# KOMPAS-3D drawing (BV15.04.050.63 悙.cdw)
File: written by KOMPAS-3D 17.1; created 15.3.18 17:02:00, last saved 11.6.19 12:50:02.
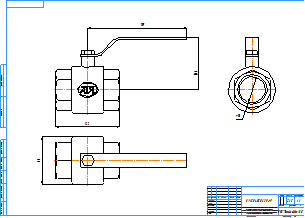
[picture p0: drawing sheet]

Sheet 1: A2, landscape

Title block, sheet 1: name: BV15.04.050.63 Р/Р; material: Внимание! Данный продукт является объектом авторского права ООО «Торговый Дом АДЛ». / Запрещается изменение, копирование, распространение / (в том числе путем копирования на другие сайты и ресурсы в Интернете) / или любое иное использование информации и объектов без предварительного / согласия правообладателя (ООО «Торговый Дом АДЛ»).; mass: 2,15; sheets: 1; organisation: ООО "Торговый дом АДЛ"; sheet format: A2; stored path: \\adlc.lan\data\АДЛ_ПКД\3D-модели\ADL production\Краны шаровые серии BV\BV15\KOMPAS 2D\BV15.04.050.63 РР.cdw

Views: Вид 1, Проекционный вид 2, Проекционный вид 3
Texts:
  kka
  adl
Dimensions and other numbers on the sheet: 122; 189; 100; 50; 90; 1:1; 1; 2,15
